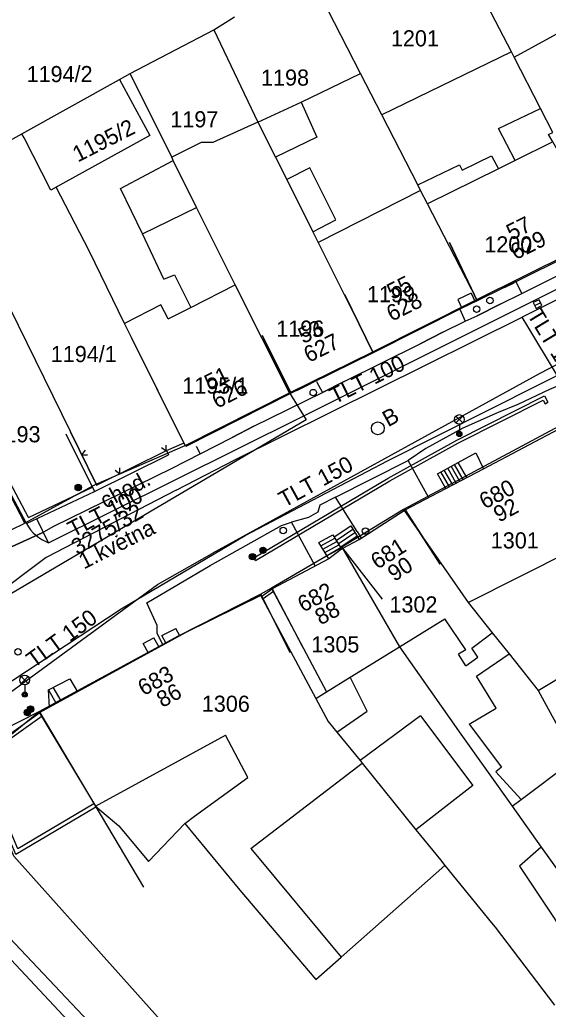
# Model space of a CAD drawing. Extents: x -601580 to 4, y -1204314 to 4.
# Drawn here: x -599977.2 to -599936.3, y -1203526.1 to -1203449.5 of the extents above; entities that cross this region are included whole.
import ezdxf

# ---------------------------------------------------------------- set-up
doc = ezdxf.new("R2010")
doc.units = 0
for name, color, linetype in [('00-KN-HRANICE PARCEL', 7, 'Continuous'), ('00-KN-PARC. CISLA', 7, 'Continuous'), ('00-KN-VNITRNI KRESBA', 7, 'Continuous'), ('00-POLOHOPIS', 7, 'Continuous'), ('00-SITE KOM. KABEL', 7, 'Continuous'), ('00-VAK-VODA-RAD IGIS', 7, 'Continuous'), ('Vrstva 25', 7, 'Continuous'), ('Vrstva 27', 7, 'Continuous'), ('Vrstva 28', 7, 'Continuous'), ('Vrstva 33', 7, 'Continuous')]:
    doc.layers.add(name, color=color, linetype=linetype)

# ---------------------------------------------------------------- blocks, each defined once
blk = doc.blocks.new('6.01A_998')
at = {"layer": 'Vrstva 25'}
for radius in [0.25, 0.2, 0.15, 0.1, 0.05]:
    blk.add_circle((0, 0), radius, dxfattribs=at)
blk = doc.blocks.new('6.01A_1000')
at = {"layer": 'Vrstva 25'}
for radius in [0.25, 0.2, 0.15, 0.1, 0.05]:
    blk.add_circle((0, 0), radius, dxfattribs=at)
blk = doc.blocks.new('6.01A_1002')
at = {"layer": 'Vrstva 25'}
for radius in [0.25, 0.2, 0.15, 0.1, 0.05]:
    blk.add_circle((0, 0), radius, dxfattribs=at)
blk = doc.blocks.new('6.560_512')
at = {"layer": 'Vrstva 33'}
for p, q in [((-0.265, 0.86), (0.265, 1.39)), ((-0.265, 1.39), (0.265, 0.86)), ((0, 0.75), (0, 0))]:
    blk.add_line(p, q, dxfattribs=at)
for centre, radius in [((0, 1.125), 0.375), ((0, 0), 0.2), ((0, 0), 0.145), ((0, 0), 0.0876)]:
    blk.add_circle(centre, radius, dxfattribs=at)
blk = doc.blocks.new('6.14A_138')
at = {"layer": 'Vrstva 28'}
blk.add_circle((0, 0), 0.25, dxfattribs=at)
blk = doc.blocks.new('6.14A_140')
at = {"layer": 'Vrstva 28'}
blk.add_circle((0, 0), 0.25, dxfattribs=at)
blk = doc.blocks.new('6.14A_142')
at = {"layer": 'Vrstva 28'}
blk.add_circle((0, 0), 0.25, dxfattribs=at)
blk = doc.blocks.new('6.14A_144')
at = {"layer": 'Vrstva 28'}
blk.add_circle((0, 0), 0.25, dxfattribs=at)
blk = doc.blocks.new('6.14A_146')
at = {"layer": 'Vrstva 28'}
blk.add_circle((0, 0), 0.25, dxfattribs=at)
blk = doc.blocks.new('6.14A_148')
at = {"layer": 'Vrstva 28'}
blk.add_circle((0, 0), 0.25, dxfattribs=at)
blk = doc.blocks.new('6.01A_1004')
at = {"layer": 'Vrstva 25'}
for radius in [0.25, 0.2, 0.15, 0.1, 0.05]:
    blk.add_circle((0, 0), radius, dxfattribs=at)
blk = doc.blocks.new('6.01A_1006')
at = {"layer": 'Vrstva 25'}
for radius in [0.25, 0.2, 0.15, 0.1, 0.05]:
    blk.add_circle((0, 0), radius, dxfattribs=at)
blk = doc.blocks.new('6.20_50')
at = {"layer": 'Vrstva 27'}
blk.add_circle((0, 0), 0.5, dxfattribs=at)
blk = doc.blocks.new('6.560_514')
at = {"layer": 'Vrstva 33'}
for p, q in [((-0.265, 0.86), (0.265, 1.39)), ((-0.265, 1.39), (0.265, 0.86)), ((0, 0.75), (0, 0))]:
    blk.add_line(p, q, dxfattribs=at)
for centre, radius in [((0, 1.125), 0.375), ((0, 0), 0.2), ((0, 0), 0.145), ((0, 0), 0.0876)]:
    blk.add_circle(centre, radius, dxfattribs=at)
blk = doc.blocks.new('6.30_78')
at = {"layer": 'Vrstva 27'}
blk.add_line((-0.25, 0), (0.25, 0), dxfattribs=at)
blk.add_lwpolyline([(-0.25, -0.25), (0.25, -0.25), (0.25, 0.25), (-0.25, 0.25)], close=True, dxfattribs=at)

msp = doc.modelspace()

# ---------------------------------------------------------------- linework, layer by layer
at = {"layer": '00-KN-HRANICE PARCEL'}
for p, q in [((-599939.12, -1203451.96), (-599945.04, -1203440.5)), ((-599950.81, -1203453.64), (-599954.85, -1203445.79)), ((-599938.91, -1203452.38), (-599927.66, -1203446.22)), ((-599962.19, -1203450.25), (-599960.57, -1203449.26)), ((-599968.67, -1203453.64), (-599962.19, -1203450.25)), ((-599962.19, -1203450.25), (-599958.76, -1203457.42)), ((-599939.12, -1203451.96), (-599949.17, -1203456.84)), ((-599938.91, -1203452.38), (-599939.12, -1203451.96)), ((-599969.49, -1203454.1), (-599968.67, -1203453.64)), ((-599965.44, -1203460.13), (-599968.67, -1203453.64)), ((-599955.41, -1203455.86), (-599950.81, -1203453.64)), ((-599949.17, -1203456.84), (-599950.81, -1203453.64)), ((-599977.06, -1203458.31), (-599969.49, -1203454.1)), ((-599958.76, -1203457.42), (-599955.41, -1203455.86)), ((-599941.8, -1203471.14), (-599931.78, -1203466.17)), ((-599978.69, -1203470.38), (-599971.29, -1203485.45)), ((-599956.31, -1203478.36), (-599960.53, -1203470.01)), ((-599949.85, -1203475.19), (-599941.8, -1203471.14)), ((-599976.82, -1203488.46), (-599984.97, -1203473.12)), ((-599964.39, -1203482.44), (-599968.57, -1203474.08)), ((-599956.31, -1203478.36), (-599949.85, -1203475.19)), ((-599964.39, -1203482.44), (-599956.31, -1203478.36)), ((-599935.36, -1203480.92), (-599947.47, -1203487.4)), ((-599971.29, -1203485.45), (-599964.39, -1203482.44)), ((-599971.29, -1203485.45), (-599976.82, -1203488.46)), ((-599947.47, -1203487.4), (-599952.26, -1203490.33)), ((-599984.64, -1203492.24), (-599976.82, -1203488.46)), ((-599975.75, -1203503.07), (-599996.01, -1203513.35)), ((-599938.36, -1203509.85), (-599934.05, -1203506.62)), ((-599939.06, -1203510.38), (-599938.36, -1203509.85)), ((-599939.06, -1203510.38), (-599936.81, -1203513.54)), ((-599936.81, -1203513.54), (-599931, -1203521.7)), ((-599944.27, -1203514.97), (-599940.67, -1203519.4))]:
    msp.add_line(p, q, dxfattribs=at)
for points in [[(-599931.78, -1203466.17), (-599935.9, -1203458.93), (-599936.23, -1203458.36), (-599935.9, -1203458.2), (-599936.86, -1203456.35), (-599938.91, -1203452.38)], [(-599969.49, -1203454.1), (-599967.14, -1203458.44), (-599974.39, -1203462.44)], [(-599941.8, -1203471.14), (-599945.62, -1203463.73), (-599946.15, -1203462.69), (-599946.37, -1203462.27), (-599949.17, -1203456.84)], [(-599958.76, -1203457.42), (-599962.25, -1203458.99), (-599963.15, -1203458.99), (-599965.44, -1203460.13)], [(-599958.76, -1203457.42), (-599957.4, -1203460.12), (-599956.53, -1203461.85), (-599954.51, -1203465.89), (-599954.09, -1203466.73), (-599949.85, -1203475.19)], [(-599978.68, -1203459.21), (-599978.64, -1203459.19), (-599977.06, -1203458.31)], [(-599974.39, -1203462.44), (-599974.8, -1203462.67), (-599976.89, -1203458.63), (-599977.06, -1203458.31)], [(-599960.53, -1203470.01), (-599963.51, -1203464.01), (-599965.32, -1203460.38), (-599965.44, -1203460.13)], [(-599968.57, -1203474.08), (-599969.09, -1203473), (-599971.83, -1203467.37), (-599974.39, -1203462.44)], [(-599956.31, -1203478.36), (-599955.02, -1203480.47), (-599982.23, -1203496.46), (-599984.64, -1203492.24)], [(-599947.47, -1203487.4), (-599942.46, -1203494.61), (-599940.6, -1203496.95), (-599939.3, -1203498.58), (-599937.04, -1203501.43)], [(-599952.26, -1203490.33), (-599957.72, -1203493.49), (-599958.59, -1203493.99)], [(-599952.26, -1203490.33), (-599947.8, -1203498.03), (-599943.03, -1203504.81), (-599939.06, -1203510.38)], [(-599958.59, -1203493.99), (-599964.95, -1203497.21), (-599975.75, -1203503.07)], [(-599958.59, -1203493.99), (-599954.27, -1203502.03), (-599953.31, -1203503.83), (-599952.64, -1203504.65), (-599950.84, -1203506.84), (-599950.67, -1203507.05), (-599946.53, -1203512.2)], [(-599937.04, -1203501.43), (-599934.74, -1203505.62), (-599934.05, -1203506.62)], [(-599948.98, -1203538.56), (-599957.44, -1203535.19), (-599961.51, -1203532.31), (-599977.69, -1203514.25), (-599980.58, -1203507), (-599975.75, -1203503.07)], [(-599975.75, -1203503.07), (-599971.34, -1203510.38), (-599969.53, -1203511.89), (-599967.24, -1203514.66), (-599964.42, -1203511.73), (-599960.17, -1203516.87), (-599954.26, -1203523.8)], [(-599946.53, -1203512.2), (-599944.62, -1203514.54), (-599944.27, -1203514.97)], [(-599957.21, -1203586.66), (-599937.08, -1203567.71), (-599952.28, -1203549.27), (-599956.27, -1203545.4), (-599985.98, -1203513.66), (-599987.68, -1203513.29), (-600018.7, -1203537.48), (-600027.97, -1203545.34), (-600031.55, -1203548.65)], [(-599936.81, -1203513.54), (-599938.5, -1203515.02), (-599932.99, -1203523.27), (-599931, -1203521.7)], [(-599954.26, -1203523.8), (-599952.31, -1203522.08), (-599944.27, -1203514.97)], [(-599940.67, -1203519.4), (-599940.38, -1203519.75), (-599935.77, -1203525.79)]]:
    msp.add_lwpolyline(points, dxfattribs=at)
at = {"layer": '00-KN-VNITRNI KRESBA'}
for p, q in [((-599955.41, -1203455.86), (-599954.2, -1203458.57)), ((-599940.12, -1203457.91), (-599936.86, -1203456.35)), ((-599938.82, -1203460.38), (-599940.12, -1203457.91)), ((-599954.2, -1203458.57), (-599957.4, -1203460.12)), ((-599935.9, -1203458.93), (-599938.82, -1203460.38)), ((-599969.41, -1203462.54), (-599965.32, -1203460.38)), ((-599946.37, -1203462.27), (-599943.15, -1203460.71)), ((-599943.15, -1203460.71), (-599942.93, -1203461.13)), ((-599942.93, -1203461.13), (-599940.67, -1203460.01)), ((-599940.67, -1203460.01), (-599940.12, -1203461.02)), ((-599938.82, -1203460.38), (-599940.12, -1203461.02)), ((-599954.73, -1203460.95), (-599956.53, -1203461.85)), ((-599952.72, -1203464.97), (-599954.73, -1203460.95)), ((-599940.12, -1203461.02), (-599945.62, -1203463.73)), ((-599967.7, -1203466.06), (-599969.41, -1203462.54)), ((-599946.15, -1203462.69), (-599954.09, -1203466.73)), ((-599967.7, -1203466.06), (-599963.51, -1203464.01)), ((-599954.51, -1203465.89), (-599952.72, -1203464.97)), ((-599966.06, -1203469.57), (-599967.7, -1203466.06)), ((-599966.06, -1203469.57), (-599965.22, -1203469.24)), ((-599965.22, -1203469.24), (-599963.97, -1203471.76)), ((-599963.97, -1203471.76), (-599960.53, -1203470.01)), ((-599966.28, -1203471.56), (-599969.09, -1203473)), ((-599965.71, -1203472.63), (-599966.28, -1203471.56)), ((-599965.71, -1203472.63), (-599963.97, -1203471.76)), ((-599942.46, -1203494.61), (-599931.65, -1203489.15)), ((-599957.72, -1203493.49), (-599953.45, -1203501.52)), ((-599947.8, -1203498.03), (-599944.28, -1203495.86)), ((-599942.65, -1203498.26), (-599944.28, -1203495.86)), ((-599942.19, -1203498.15), (-599940.6, -1203496.95)), ((-599951.62, -1203500.39), (-599947.8, -1203498.03)), ((-599941.71, -1203498.85), (-599942.19, -1203498.15)), ((-599942.65, -1203498.26), (-599943.21, -1203498.61)), ((-599942.66, -1203499.51), (-599943.21, -1203498.61)), ((-599942.66, -1203499.51), (-599941.71, -1203498.85)), ((-599941.82, -1203500.31), (-599939.3, -1203498.58)), ((-599937.04, -1203501.43), (-599932.93, -1203498.91)), ((-599953.45, -1203501.52), (-599951.62, -1203500.39)), ((-599950.29, -1203503.01), (-599951.62, -1203500.39)), ((-599940.29, -1203502.79), (-599941.82, -1203500.31)), ((-599954.27, -1203502.03), (-599953.45, -1203501.52)), ((-599942.38, -1203504.02), (-599940.29, -1203502.79)), ((-599952.64, -1203504.65), (-599950.29, -1203503.01)), ((-599946.17, -1203503.39), (-599950.84, -1203506.84)), ((-599946.17, -1203503.39), (-599942.1, -1203508.78)), ((-599942.38, -1203504.02), (-599939.88, -1203507.35)), ((-599971.34, -1203510.38), (-599961.27, -1203504.88)), ((-599959.55, -1203508.15), (-599961.27, -1203504.88)), ((-599959.31, -1203513.66), (-599950.67, -1203507.05)), ((-599939.88, -1203507.35), (-599940.33, -1203507.73)), ((-599963.68, -1203511.16), (-599959.55, -1203508.15)), ((-599938.36, -1203509.85), (-599940.33, -1203507.73)), ((-599942.1, -1203508.78), (-599946.53, -1203512.2)), ((-599964.42, -1203511.73), (-599963.68, -1203511.16)), ((-599959.31, -1203513.66), (-599952.31, -1203522.08))]:
    msp.add_line(p, q, dxfattribs=at)
at = {"layer": '00-POLOHOPIS'}
for p, q in [((-599941.023, -1203473.043), (-599919.338, -1203462.252)), ((-599938.937, -1203469.868), (-599939.671, -1203470.234)), ((-599942.24, -1203470.655), (-599943.269, -1203471.145)), ((-599942.24, -1203470.655), (-599941.922, -1203471.323)), ((-599943.269, -1203471.145), (-599942.951, -1203471.813)), ((-599936.921, -1203477.686), (-599923.167, -1203470.856)), ((-599976.702, -1203488.499), (-599985.128, -1203472.668)), ((-599976.541, -1203488.014), (-599984.506, -1203473.048)), ((-599955.361, -1203480.224), (-599941.023, -1203473.043)), ((-599955.74, -1203478.192), (-599954.655, -1203477.654)), ((-599948.715, -1203483.642), (-599936.921, -1203477.686)), ((-599943.342, -1203482.027), (-599936.556, -1203478.603)), ((-599943.225, -1203482.248), (-599936.658, -1203478.934)), ((-599936.658, -1203478.934), (-599936.502, -1203479.216)), ((-599936.556, -1203478.603), (-599936.283, -1203479.095)), ((-599936.502, -1203479.216), (-599936.283, -1203479.095)), ((-599974.981, -1203489.973), (-599955.361, -1203480.224)), ((-599973.644, -1203481.531), (-599971.43, -1203486.014)), ((-599948.659, -1203484.979), (-599943.342, -1203482.027)), ((-599965.847, -1203482.844), (-599964.475, -1203482.246)), ((-599965.847, -1203482.844), (-599965.683, -1203483.176)), ((-599948.532, -1203485.195), (-599943.225, -1203482.248)), ((-599971.43, -1203486.014), (-599965.683, -1203483.176)), ((-599959.754, -1203489.42), (-599948.715, -1203483.642)), ((-599943.245, -1203483.759), (-599941.872, -1203483.012)), ((-599941.872, -1203483.012), (-599941.289, -1203484.261)), ((-599944.844, -1203484.639), (-599943.245, -1203483.759)), ((-599943.656, -1203485.505), (-599944.318, -1203484.35)), ((-599943.391, -1203485.365), (-599944.055, -1203484.205)), ((-599943.125, -1203485.226), (-599943.792, -1203484.06)), ((-599942.859, -1203485.086), (-599943.53, -1203483.916)), ((-599942.571, -1203484.935), (-599943.245, -1203483.759)), ((-599959.088, -1203491.145), (-599948.659, -1203484.979)), ((-599958.961, -1203491.36), (-599948.532, -1203485.195)), ((-599944.188, -1203485.784), (-599944.844, -1203484.639)), ((-599943.922, -1203485.644), (-599944.581, -1203484.494)), ((-599976.541, -1203488.014), (-599971.588, -1203485.679)), ((-599976.702, -1203488.499), (-599971.43, -1203486.014)), ((-599974.981, -1203489.973), (-599975.884, -1203488.113)), ((-599952.841, -1203489.532), (-599951.557, -1203488.676)), ((-599952.7, -1203489.798), (-599951.398, -1203488.931)), ((-599951.557, -1203488.676), (-599950.909, -1203489.714)), ((-599969.361, -1203495.095), (-599959.754, -1203489.42)), ((-599954.042, -1203489.967), (-599952.961, -1203489.364)), ((-599953.885, -1203490.223), (-599952.806, -1203489.621)), ((-599952.961, -1203489.364), (-599952.29, -1203490.478)), ((-599952.545, -1203490.056), (-599951.239, -1203489.185)), ((-599952.39, -1203490.313), (-599951.08, -1203489.44)), ((-599953.266, -1203491.234), (-599954.042, -1203489.967)), ((-599953.728, -1203490.479), (-599952.651, -1203489.878)), ((-599953.572, -1203490.735), (-599952.497, -1203490.135)), ((-599953.415, -1203490.991), (-599952.342, -1203490.393)), ((-599958.961, -1203491.36), (-599959.088, -1203491.145)), ((-599958.45, -1203494.109), (-599957.656, -1203493.554)), ((-599958.36, -1203494.29), (-599957.562, -1203493.732)), ((-599978.837, -1203501.306), (-599969.361, -1203495.095)), ((-599966.209, -1203497.154), (-599965.133, -1203496.608)), ((-599964.814, -1203497.19), (-599965.133, -1203496.608)), ((-599967.667, -1203497.77), (-599966.835, -1203497.329)), ((-599966.427, -1203498.074), (-599966.835, -1203497.329)), ((-599965.872, -1203497.769), (-599966.209, -1203497.154)), ((-599967.252, -1203498.526), (-599967.667, -1203497.77)), ((-599974.998, -1203501.365), (-599973.33, -1203500.505)), ((-599973.33, -1203500.505), (-599972.741, -1203501.535)), ((-599974.651, -1203501.166), (-599974.041, -1203502.232)), ((-599974.914, -1203502.716), (-599974.998, -1203501.365)), ((-599974.998, -1203501.365), (-599974.389, -1203502.43))]:
    msp.add_line(p, q, dxfattribs=at)
for points in [[(-599933.95, -1203461.798), (-599931.731, -1203466.279), (-599941.757, -1203471.244), (-599943.908, -1203466.73)], [(-599943.908, -1203466.73), (-599941.757, -1203471.244), (-599942.951, -1203471.813), (-599949.82, -1203475.271), (-599952.027, -1203470.784)], [(-599952.027, -1203470.784), (-599949.82, -1203475.271), (-599956.175, -1203478.397), (-599958.426, -1203473.932)], [(-599958.426, -1203473.932), (-599956.175, -1203478.397), (-599964.342, -1203482.515), (-599966.593, -1203478.05)], [(-599973.312, -1203481.367), (-599971.262, -1203485.518)], [(-599944.647, -1203491.646), (-599947.339, -1203487.433), (-599944.188, -1203485.784), (-599941.289, -1203484.261), (-599935.023, -1203480.941), (-599930.576, -1203488.881)], [(-599972.156, -1203482.804), (-599972.426, -1203483.16), (-599971.979, -1203483.162)], [(-599971.262, -1203485.518), (-599965.847, -1203482.844)], [(-599966.239, -1203482.592), (-599965.882, -1203482.862), (-599965.88, -1203482.414)], [(-599969.825, -1203484.363), (-599969.469, -1203484.633), (-599969.466, -1203484.186)], [(-599949.115, -1203494.337), (-599952.191, -1203490.395), (-599950.909, -1203489.714), (-599947.339, -1203487.433), (-599944.647, -1203491.646)], [(-599969.836, -1203489.457), (-599969.706, -1203489.511), (-599969.668, -1203489.376)], [(-599949.115, -1203494.337), (-599952.191, -1203490.395), (-599953.266, -1203491.234), (-599957.656, -1203493.554), (-599955.32, -1203497.975)], [(-599956.268, -1203498.509), (-599958.489, -1203494.029), (-599964.339, -1203496.929), (-599972.741, -1203501.535), (-599974.914, -1203502.716), (-599975.657, -1203503.131), (-599967.629, -1203516.652)], [(-599971.316, -1203510.443), (-599977.516, -1203514.124), (-599980.656, -1203506.686), (-599975.657, -1203503.131)], [(-599971.469, -1203510.185), (-599977.373, -1203513.69), (-599980.286, -1203506.791), (-599975.483, -1203503.375)]]:
    msp.add_lwpolyline(points, dxfattribs=at)
msp.add_arc((-599973.914, -1203486.986), 3.172, 208.49292, 250.34837, dxfattribs=at)
at = {"layer": '00-SITE KOM. KABEL'}
for points in [[(-599938.31, -1203470.67), (-599927.98, -1203465.51), (-599926.12, -1203464.62), (-599921.58, -1203462.35)], [(-599938.76, -1203469.76), (-599938.31, -1203470.67)], [(-599942.71, -1203472.83), (-599941.76, -1203472.41), (-599939.98, -1203471.51), (-599938.31, -1203470.67)], [(-599943.12, -1203471.9), (-599942.71, -1203472.83)], [(-599939.98, -1203471.51), (-599941.76, -1203472.41)], [(-599953.76, -1203478.33), (-599952.07, -1203477.49), (-599946.19, -1203474.57), (-599944.44, -1203473.67), (-599942.71, -1203472.83)], [(-599944.44, -1203473.67), (-599946.19, -1203474.57)], [(-599931.26, -1203475.98), (-599932.65, -1203476.65), (-599936.17, -1203478.12), (-599938.62, -1203479.26), (-599940.13, -1203479.88), (-599942.88, -1203481.1), (-599945.74, -1203482.68), (-599947.12, -1203483.62)], [(-599954.23, -1203477.49), (-599953.76, -1203478.33)], [(-599952.07, -1203477.49), (-599953.76, -1203478.33)], [(-599963.24, -1203483.09), (-599960.76, -1203481.83), (-599959.07, -1203480.96), (-599953.76, -1203478.33)], [(-599959.07, -1203480.96), (-599960.76, -1203481.83)], [(-599963.55, -1203482.5), (-599963.24, -1203483.09)], [(-599986.98, -1203497.58), (-599986.37, -1203497.1), (-599985.53, -1203496.48), (-599984.42, -1203494.9), (-599984.02, -1203493.51), (-599983.72, -1203492.96), (-599975.47, -1203489.21), (-599974.62, -1203488.72), (-599965.4, -1203484.2), (-599963.24, -1203483.09)], [(-599952.74, -1203486.45), (-599947.12, -1203483.62)], [(-599945.54, -1203486.45), (-599947.12, -1203483.62)], [(-599952.74, -1203486.45), (-599953.97, -1203487.08), (-599954.13, -1203487.61), (-599954.85, -1203488.02), (-599956.15, -1203488.39)], [(-599951.077, -1203489.104), (-599952.74, -1203486.45)], [(-599966.11, -1203497.9), (-599966.56, -1203497.01), (-599966.58, -1203496.39), (-599967.37, -1203494.62), (-599962.46, -1203491.73), (-599956.93, -1203488.65), (-599956.15, -1203488.39)], [(-599954.33, -1203491.77), (-599956.15, -1203488.39)], [(-599975.47, -1203489.21), (-599983.72, -1203492.96)], [(-599951.077, -1203489.104), (-599950.758, -1203489.613), (-599950.067, -1203489.172)], [(-599951.077, -1203489.104), (-599950.758, -1203489.613), (-599950.067, -1203489.172)], [(-599946.97, -1203552.96), (-599947.92, -1203551.91), (-599950.7, -1203549), (-599951.21, -1203548.75), (-599952.07, -1203548.17), (-599956.02, -1203543.8), (-599963.99, -1203535.42), (-599980.23, -1203518.24), (-599985.53, -1203512.82), (-599988.04, -1203510.93), (-599989.41, -1203509.72), (-599994.23, -1203503.41), (-599994.29, -1203503.06)], [(-599946.97, -1203552.96), (-599947.92, -1203551.91), (-599950.7, -1203549), (-599951.21, -1203548.75), (-599952.07, -1203548.17), (-599956.02, -1203543.8), (-599963.99, -1203535.42), (-599980.23, -1203518.24), (-599985.53, -1203512.82), (-599988.04, -1203510.93), (-599989.41, -1203509.72), (-599994.23, -1203503.41), (-599994.29, -1203503.06)]]:
    msp.add_lwpolyline(points, dxfattribs=at)
at = {"layer": '00-VAK-VODA-RAD IGIS'}
for points in [[(-599736.917, -1203391.349), (-599751.99, -1203394.59), (-599762.03, -1203397.11), (-599770.82, -1203399.95), (-599780.929, -1203403.567), (-599786.02, -1203405.496), (-599790.989, -1203407.409), (-599793.256, -1203408.295), (-599803.27, -1203412.231), (-599806.056, -1203413.327), (-599817.099, -1203417.917), (-599817.418, -1203418.049), (-599818.78, -1203418.672), (-599820.596, -1203419.503), (-599835.69, -1203426.41), (-599857.929, -1203437.515), (-599863.753, -1203440.423), (-599875.065, -1203446.063), (-599904.229, -1203460.514), (-599915.088, -1203465.894), (-599929.431, -1203473.001), (-599929.758, -1203473.167), (-599936.908, -1203476.866), (-599962.31, -1203490.81)], [(-599735.93, -1203391.73), (-599751.96, -1203394.97), (-599761.97, -1203397.51), (-599770.82, -1203400.29), (-599782.03, -1203404.36), (-599791.55, -1203408.01), (-599806, -1203413.76), (-599817.36, -1203418.46), (-599835.49, -1203426.95), (-599872.84, -1203445.59), (-599889.534, -1203453.919), (-599889.712, -1203454.008), (-599929.34, -1203473.78), (-599935.62, -1203476.92), (-599937.847, -1203473.233), (-599938.29, -1203472.5)], [(-599861.057, -1203434.129), (-599861.177, -1203434.189), (-599861.72, -1203434.46), (-599862.392, -1203434.796), (-599862.716, -1203434.958), (-599870.534, -1203438.863), (-599871.43, -1203439.31), (-599879.068, -1203443.11), (-599897.102, -1203452.083), (-599904.19, -1203455.61), (-599916.591, -1203461.746), (-599924.538, -1203465.678), (-599938.29, -1203472.5)], [(-599965.1, -1203485.9), (-599960.553, -1203483.562), (-599938.29, -1203472.5)], [(-599965.1, -1203485.9), (-599975.16, -1203491.11), (-599979.468, -1203494.319)], [(-600070.95, -1203584.1), (-600070.85, -1203583.99), (-600051.66, -1203564.1), (-600035.84, -1203547.76), (-600028.86, -1203540.72), (-600026.49, -1203538.32), (-600021.27, -1203535.96), (-600010.43, -1203526.89), (-600001.83, -1203519.81), (-599988.68, -1203509.4), (-599966.54, -1203493.21), (-599962.31, -1203490.81)]]:
    msp.add_lwpolyline(points, dxfattribs=at)

# ---------------------------------------------------------------- block references
at = {"layer": '00-POLOHOPIS', "rotation": -90.00000000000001}
for name, p in [('6.14A_148', (-599940.777, -1203471.217)), ('6.14A_146', (-599941.808, -1203471.891)), ('6.14A_140', (-599954.472, -1203478.35)), ('6.20_50', (-599949.465, -1203481.114)), ('6.01A_998', (-599972.684, -1203485.7)), ('6.14A_142', (-599956.798, -1203489.025)), ('6.14A_144', (-599950.421, -1203489.071)), ('6.01A_1004', (-599958.367, -1203490.564)), ('6.01A_1006', (-599959.187, -1203491.057)), ('6.14A_138', (-599977.357, -1203498.426)), ('6.01A_1000', (-599976.378, -1203502.858)), ('6.01A_1002', (-599976.631, -1203503.124))]:
    msp.add_blockref(name, p, dxfattribs=at)
at = {"layer": '00-POLOHOPIS', "xscale": 0.99999982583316, "yscale": 0.9999998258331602, "rotation": 25.913556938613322}
msp.add_blockref('6.30_78', (-599937.092, -1203471.496), dxfattribs=at)
at = {"layer": '00-POLOHOPIS'}
for name, p in [('6.560_514', (-599943.148, -1203481.556)), ('6.560_512', (-599976.834, -1203501.732))]:
    msp.add_blockref(name, p, dxfattribs=at)

# ---------------------------------------------------------------- texts
at = {"layer": '00-KN-PARC. CISLA'}
for s, p in [('1201', (-599948.454, -1203451.54)), ('1194/2', (-599976.69, -1203454.31)), ('1198', (-599958.517, -1203454.58)), ('1197', (-599965.547, -1203457.81)), ('1200', (-599941.217, -1203467.5)), ('1199', (-599950.307, -1203471.35)), ('1196', (-599957.337, -1203474.02)), ('1194/1', (-599974.815, -1203475.99)), ('1195/1', (-599964.625, -1203478.43)), ('1193', (-599979.327, -1203482.2)), ('1301', (-599940.714, -1203490.42)), ('1302', (-599948.567, -1203495.38)), ('1305', (-599954.617, -1203498.47)), ('1306', (-599963.107, -1203503.07))]:
    msp.add_text(s, height=1.25, dxfattribs=at).set_placement(p)
for s, rotation, p in [('1195/2', 27, (-599972.72, -1203460.543)), ('3275/32', 30, (-599972.758, -1203490.97))]:
    msp.add_text(s, height=1.25, rotation=rotation, dxfattribs=at).set_placement(p)
at = {"layer": '00-POLOHOPIS'}
for s, rotation, p in [('57', 26.34519, (-599939.112, -1203466.586)), ('629', 26.34519, (-599938.794, -1203468.102)), ('55', 26.72165, (-599948.363, -1203471.179)), ('628', 26.72165, (-599948.392, -1203472.873)), ('53', 26.19239, (-599955.249, -1203474.599)), ('627', 26.19239, (-599954.816, -1203476.057)), ('51', 26.75835, (-599962.506, -1203478.229)), ('626', 26.75835, (-599961.928, -1203479.617)), ('chod.', 28.04105, (-599970.564, -1203487.36)), ('680', 27.71535, (-599941.184, -1203487.405)), ('92', 27.91659, (-599940.079, -1203488.43)), ('1.kvetna', 26.72686, (-599972.248, -1203492.06)), ('681', 32.57596, (-599949.505, -1203492.08)), ('90', 32.57596, (-599948.194, -1203493.023)), ('682', 27.85528, (-599955.257, -1203495.397)), ('88', 27.85528, (-599953.918, -1203496.386)), ('683', 28.73168, (-599967.622, -1203501.865)), ('86', 28.73168, (-599966.173, -1203502.781))]:
    msp.add_text(s, height=1.25, rotation=rotation, dxfattribs=at).set_placement(p)
at = {"layer": '00-VAK-VODA-RAD IGIS'}
for s, rotation, p in [('TLT 100', 301.14, (-599937.93, -1203472.322)), ('TLT 100', 26.42, (-599952.812, -1203479.27)), ('B', 28.76, (-599948.671, -1203481.042)), ('TLT 150', 28.76, (-599956.713, -1203487.282)), ('TLT 100', 27.38, (-599973.086, -1203489.585)), ('TLT 150', 36.18, (-599976.123, -1203499.722))]:
    msp.add_text(s, height=1.25, rotation=rotation, dxfattribs=at).set_placement(p)

doc.saveas('drawing.dxf')
